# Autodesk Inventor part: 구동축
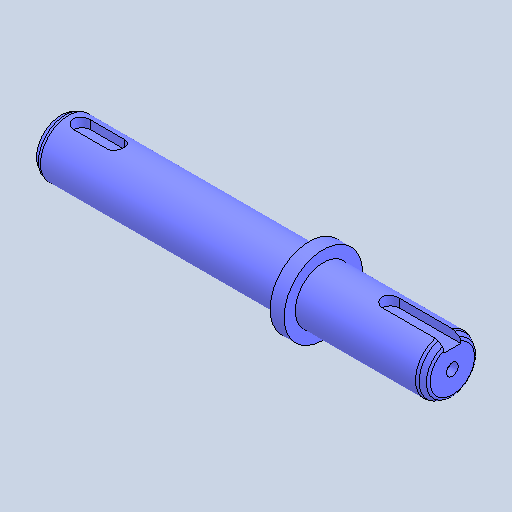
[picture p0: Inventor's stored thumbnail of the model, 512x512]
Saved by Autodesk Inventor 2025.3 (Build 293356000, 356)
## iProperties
Created: 2026-01
Part Number: 구동축
Material: 강철, 탄소
Document SubType Name: Modeling
Designer: pc6
Density: 7.85 g/cm^3
Appearance: 기본값
Author: jhkim
Sending System: Autodesk Inventor 2026
Preprocessor: ST-DEVELOPER v20.1
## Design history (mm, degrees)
feature "솔리드1"
node "솔리드2"
